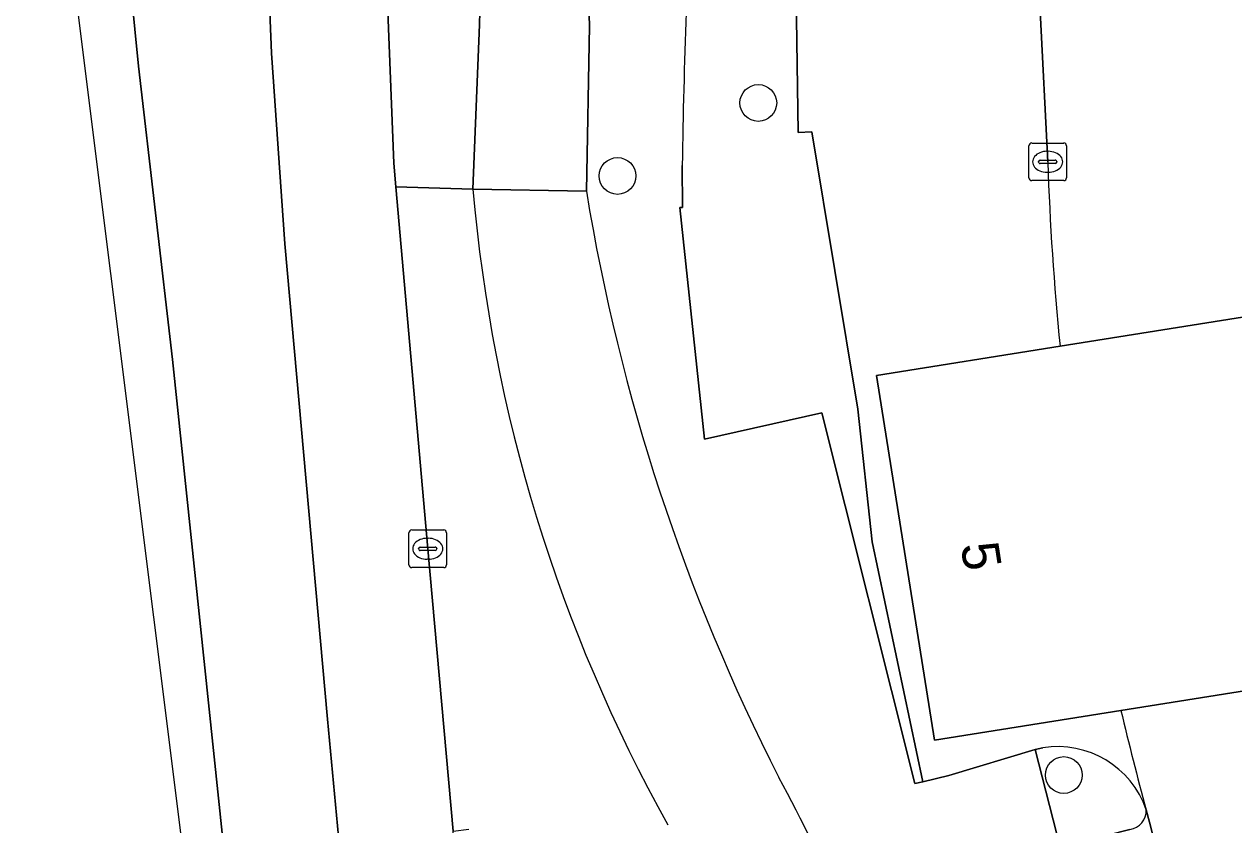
# Model space of a CAD drawing. Extents: x 160675 to 161153, y 383241 to 383714.
# Drawn here: x 160675.32 to 160707.51, y 383474.35 to 383495.64 of the extents above; entities that cross this region are included whole.
import ezdxf

# ---------------------------------------------------------------- set-up
doc = ezdxf.new("R2010")
doc.units = 0
for name, color, linetype in [('IMGEO_Berm_groen', 7, 'Continuous'), ('IMGEO_Berm_open', 7, 'Continuous'), ('IMGEO_Boom', 7, 'Continuous'), ('IMGEO_Erf', 7, 'Continuous'), ('IMGEO_Fietspad_gesloten', 7, 'Continuous'), ('IMGEO_Groenvoorziening', 7, 'Continuous'), ('IMGEO_Kolk', 7, 'Continuous'), ('IMGEO_Pand', 7, 'Continuous'), ('IMGEO_Pand_nummerreeks', 7, 'Continuous'), ('IMGEO_Parkeervlak_open', 7, 'Continuous'), ('IMGEO_Rijbaan_lokaal_gesloten', 7, 'Continuous'), ('IMGEO_Rijbaan_lokaal_open', 7, 'Continuous'), ('IMGEO_Voetpad_open', 7, 'Continuous')]:
    doc.layers.add(name, color=color, linetype=linetype)

msp = doc.modelspace()

# ---------------------------------------------------------------- linework, layer by layer
at = {"layer": 'IMGEO_Berm_groen'}
msp.add_lwpolyline([(160687.262, 383491.252), (160685.215, 383491.312), (160686.06, 383481.687), (160686.733, 383474.175), (160687.15, 383474.227)], dxfattribs=at)
msp.add_arc((160729.158, 383494.859), 42.051, 184.9205, 209.1949, dxfattribs=at)
at = {"layer": 'IMGEO_Berm_open'}
msp.add_lwpolyline([(160684.974, 383496.66), (160685.161, 383491.941), (160685.215, 383491.312), (160687.262, 383491.252), (160687.435, 383495.626), (160687.47, 383496.982), (160687.684, 383500)], dxfattribs=at)
at = {"layer": 'IMGEO_Boom'}
for centre in [(160694.855, 383493.542), (160691.108, 383491.601), (160702.982, 383475.67)]:
    msp.add_circle(centre, 0.489, dxfattribs=at)
at = {"layer": 'IMGEO_Erf'}
for points in [[(160709.795, 383478.231), (160704.503, 383477.389)], [(160705.177, 383474.744), (160705.266, 383474.42), (160707.356, 383466.299), (160708.003, 383463.693), (160708.065, 383463.57), (160708.125, 383463.446)]]:
    msp.add_lwpolyline(points, dxfattribs=at)
msp.add_arc((160778.529, 383494.844), 76.056, 193.26771, 195.32407, dxfattribs=at)
at = {"layer": 'IMGEO_Fietspad_gesloten'}
for points in [[(160687.684, 383500), (160687.47, 383496.982), (160687.435, 383495.626), (160687.262, 383491.252), (160690.28, 383491.194), (160690.363, 383495.591), (160690.332, 383496.702), (160690.426, 383500)], [(160690.28, 383491.194), (160687.262, 383491.252)]]:
    msp.add_lwpolyline(points, dxfattribs=at)
for centre, radius, start, end in [((160729.158, 383494.859), 42.051, 184.9205, 209.1949), ((160742.86, 383499.837), 53.286, 189.3349, 207.0446), ((160656.668, 383454.622), 44.053, 18.2387, 28.4501)]:
    msp.add_arc(centre, radius, start, end, dxfattribs=at)
at = {"layer": 'IMGEO_Groenvoorziening'}
for points in [[(160692.83, 383491.882), (160692.834, 383490.761), (160692.77, 383490.76), (160693.427, 383484.601), (160696.549, 383485.302), (160699.019, 383475.443), (160699.23, 383475.493), (160697.887, 383481.87), (160697.5, 383485.396), (160696.281, 383492.774), (160695.913, 383492.755), (160695.755, 383503.66)], [(160702.426, 383476.395), (160702.218, 383476.346), (160702.882, 383473.753), (160704.742, 383474.226)]]:
    msp.add_lwpolyline(points, dxfattribs=at)
for centre, radius, start, end in [((160850.842, 383489.699), 158.027, 176.26262, 179.20858), ((160702.817, 383473.93), 2.496, 19.0364, 99.0239), ((160704.664, 383474.733), 0.513, 278.6966, 1.2584)]:
    msp.add_arc(centre, radius, start, end, dxfattribs=at)
at = {"layer": 'IMGEO_Kolk'}
for p, q in [((160702.053, 383491.551), (160702.053, 383492.403)), ((160702.128, 383492.477), (160702.98, 383492.477)), ((160703.054, 383492.403), (160703.054, 383491.551)), ((160702.355, 383492.02), (160702.753, 383492.02)), ((160702.541, 383492.257), (160702.566, 383492.257)), ((160702.312, 383491.971), (160702.312, 383491.983)), ((160702.75, 383491.934), (160702.352, 383491.934)), ((160702.564, 383491.697), (160702.539, 383491.697)), ((160702.796, 383491.983), (160702.796, 383491.971)), ((160702.98, 383491.477), (160702.128, 383491.477)), ((160685.559, 383481.261), (160685.559, 383482.113)), ((160685.634, 383482.187), (160686.486, 383482.187)), ((160686.56, 383482.113), (160686.56, 383481.261)), ((160685.861, 383481.73), (160686.259, 383481.73)), ((160686.047, 383481.967), (160686.072, 383481.967)), ((160685.818, 383481.681), (160685.818, 383481.693)), ((160686.256, 383481.644), (160685.858, 383481.644)), ((160686.07, 383481.407), (160686.045, 383481.407)), ((160686.302, 383481.693), (160686.302, 383481.681)), ((160686.486, 383481.187), (160685.634, 383481.187))]:
    msp.add_line(p, q, dxfattribs=at)
for points in [[(160702.053, 383491.551), (160702.053, 383492.403)], [(160702.128, 383492.477), (160702.98, 383492.477)], [(160703.054, 383492.403), (160703.054, 383491.551)], [(160702.98, 383491.477), (160702.128, 383491.477)], [(160685.559, 383481.261), (160685.559, 383482.113)], [(160685.634, 383482.187), (160686.486, 383482.187)], [(160686.56, 383482.113), (160686.56, 383481.261)], [(160686.486, 383481.187), (160685.634, 383481.187)]]:
    msp.add_lwpolyline(points, dxfattribs=at)
for centre, radius, start, end in [((160702.13, 383492.401), 0.0765, 91.552, 178.448), ((160702.13, 383492.401), 0.0765, 91.552, 178.448), ((160702.978, 383492.401), 0.0765, 1.552, 88.448), ((160702.978, 383492.401), 0.0765, 1.552, 88.448), ((160702.352, 383491.98), 0.0403, 85.8775, 175.7526), ((160702.757, 383491.982), 0.0386, 1.7309, 96.639), ((160702.349, 383491.97), 0.0366, 178.938, 274.7102), ((160702.753, 383491.977), 0.043, 264.8664, 352.4533), ((160702.13, 383491.553), 0.0765, 181.552, 268.448), ((160702.13, 383491.553), 0.0765, 181.552, 268.448), ((160702.978, 383491.553), 0.0765, 271.552, 358.448), ((160702.978, 383491.553), 0.0765, 271.552, 358.448), ((160685.636, 383482.111), 0.0765, 91.552, 178.448), ((160685.636, 383482.111), 0.0765, 91.552, 178.448), ((160686.484, 383482.111), 0.0765, 1.552, 88.448), ((160686.484, 383482.111), 0.0765, 1.552, 88.448), ((160685.858, 383481.69), 0.0403, 85.8775, 175.7526), ((160686.263, 383481.692), 0.0386, 1.7309, 96.639), ((160685.855, 383481.68), 0.0366, 178.938, 274.7102), ((160686.259, 383481.687), 0.043, 264.8664, 352.4533), ((160685.636, 383481.263), 0.0765, 181.552, 268.448), ((160685.636, 383481.263), 0.0765, 181.552, 268.448), ((160686.484, 383481.263), 0.0765, 271.552, 358.448), ((160686.484, 383481.263), 0.0765, 271.552, 358.448)]:
    msp.add_arc(centre, radius, start, end, dxfattribs=at)
for centre, major_axis, ratio, start_param, end_param in [((160702.54, 383491.977), (-0.387, 0.002), 0.722429, 4.712389, 7.853982), ((160702.565, 383491.977), (-0.39, 0.002), 0.717154, 1.570796, 4.712389), ((160686.046, 383481.687), (-0.387, 0.002), 0.722429, 4.712389, 7.853982), ((160686.071, 383481.687), (-0.39, 0.002), 0.717154, 1.570796, 4.712389)]:
    msp.add_ellipse(centre, major_axis=major_axis, ratio=ratio, start_param=start_param, end_param=end_param, dxfattribs=at)
at = {"layer": 'IMGEO_Pand'}
msp.add_lwpolyline([(160716.372, 383489.219), (160713.852, 383488.823), (160709.132, 383488.067), (160702.884, 383487.072), (160698.001, 383486.295), (160699.544, 383476.6), (160704.503, 383477.389), (160709.795, 383478.231), (160711.188, 383478.453), (160717.884, 383479.519)], close=True, dxfattribs=at)
at = {"layer": 'IMGEO_Parkeervlak_open'}
for points in [[(160700.187, 383520.697), (160695.873, 383520.826), (160695.791, 383518.013), (160695.791, 383516.533), (160695.755, 383503.793), (160695.755, 383503.66), (160695.913, 383492.755), (160696.281, 383492.774), (160697.5, 383485.396), (160697.887, 383481.87), (160699.23, 383475.493), (160699.925, 383475.656), (160702.218, 383476.346), (160702.426, 383476.395)], [(160702.555, 383491.973), (160702.151, 383500), (160701.542, 383512.084)], [(160704.503, 383477.389), (160699.544, 383476.6), (160698.001, 383486.295), (160702.884, 383487.072)]]:
    msp.add_lwpolyline(points, dxfattribs=at)
for centre, radius, start, end in [((160776.861, 383494.5), 74.349, 181.94743, 185.73348), ((160778.529, 383494.844), 76.056, 193.26771, 195.32407), ((160702.817, 383473.93), 2.496, 19.0364, 99.0239)]:
    msp.add_arc(centre, radius, start, end, dxfattribs=at)
at = {"layer": 'IMGEO_Rijbaan_lokaal_gesloten'}
for points in [[(160695.008, 383574.126), (160700.015, 383581.605), (160701.217, 383583.225), (160702.452, 383584.824), (160718.729, 383604.358), (160717.907, 383605.036), (160709.688, 383595.022), (160696.528, 383578.802), (160695.17, 383577.128), (160686.295, 383560.103), (160678.578, 383539.845), (160675.636, 383523.856), (160675.457, 383514.427), (160675.323, 383507.364), (160681.062, 383461.517), (160687.429, 383392.401), (160690.846, 383309.913), (160690.823, 383309.426)], [(160692.143, 383416.193), (160688.604, 383454.352), (160688.451, 383455.817), (160686.733, 383474.175), (160686.06, 383481.687), (160685.215, 383491.312), (160685.161, 383491.941), (160684.974, 383496.66), (160684.835, 383499.113), (160684.757, 383502.656), (160684.867, 383507.93), (160685.459, 383515.912), (160686.35, 383522.561), (160687.563, 383528.543), (160689.355, 383535.536)], [(160686.021, 383534.678), (160685.454, 383532.715), (160684.662, 383529.599), (160684.062, 383526.862), (160683.468, 383523.707), (160683.016, 383520.889), (160682.478, 383516.818), (160682.012, 383511.753), (160681.744, 383505.743), (160681.705, 383499.702), (160681.902, 383494.869), (160682.26, 383489.795), (160683.396, 383477.158), (160687.968, 383428.367)], [(160687.968, 383428.367), (160683.396, 383477.158), (160682.26, 383489.795), (160681.902, 383494.869), (160681.705, 383499.702), (160681.744, 383505.743), (160682.012, 383511.753), (160682.478, 383516.818), (160683.016, 383520.889), (160683.468, 383523.707), (160684.062, 383526.862), (160684.662, 383529.599), (160685.454, 383532.715), (160686.021, 383534.678)], [(160678.192, 383502.378), (160677.594, 383502.312), (160678.36, 383494.517), (160679.265, 383486.721), (160680.726, 383472.857), (160682.063, 383458.998), (160683.55, 383442.888), (160685.127, 383426.54), (160686.903, 383407.316), (160688.615, 383388.908), (160689.022, 383384.71), (160689.288, 383381.799), (160691.239, 383361.074), (160692.206, 383350.414), (160693.005, 383340.304), (160694.063, 383326.735), (160694.984, 383313.282)], [(160690.823, 383309.426), (160691.536, 383309.351), (160691.49, 383311.745), (160691.097, 383321.255), (160690.843, 383327.367), (160689.89, 383351.359), (160689.107, 383372.169), (160688.604, 383384.621), (160688.615, 383388.908), (160686.903, 383407.316), (160685.127, 383426.54), (160683.55, 383442.888), (160682.063, 383458.998), (160680.726, 383472.857), (160679.265, 383486.721), (160678.36, 383494.517), (160677.594, 383502.312), (160676.94, 383502.24)]]:
    msp.add_lwpolyline(points, dxfattribs=at)
at = {"layer": 'IMGEO_Rijbaan_lokaal_open'}
for points in [[(160702.884, 383487.072), (160709.132, 383488.067), (160708.607, 383500), (160708.008, 383513.62), (160707.953, 383514.866), (160707.714, 383519.975)], [(160701.542, 383512.084), (160702.151, 383500), (160702.555, 383491.973)]]:
    msp.add_lwpolyline(points, dxfattribs=at)
msp.add_arc((160776.861, 383494.5), 74.349, 181.94743, 185.73348, dxfattribs=at)
at = {"layer": 'IMGEO_Voetpad_open'}
for points in [[(160690.426, 383500), (160690.332, 383496.702), (160690.363, 383495.591), (160690.28, 383491.194)], [(160704.742, 383474.226), (160702.882, 383473.753), (160702.218, 383476.346), (160699.925, 383475.656), (160699.23, 383475.493), (160699.019, 383475.443), (160696.549, 383485.302), (160693.427, 383484.601), (160692.77, 383490.76), (160692.834, 383490.761), (160692.83, 383491.882)], [(160707.356, 383466.299), (160705.266, 383474.42), (160705.177, 383474.744)]]:
    msp.add_lwpolyline(points, dxfattribs=at)
for centre, radius, start, end in [((160850.842, 383489.699), 158.027, 176.26262, 179.20858), ((160742.86, 383499.837), 53.286, 189.3349, 207.0446), ((160656.668, 383454.622), 44.053, 18.2387, 28.4501), ((160704.664, 383474.733), 0.513, 278.6966, 1.2584)]:
    msp.add_arc(centre, radius, start, end, dxfattribs=at)

# ---------------------------------------------------------------- texts
at = {"layer": 'IMGEO_Pand_nummerreeks'}
msp.add_text('5', height=1, rotation=278.8463, dxfattribs=at).set_placement((160700.238, 383481.789))

doc.saveas('drawing.dxf')
